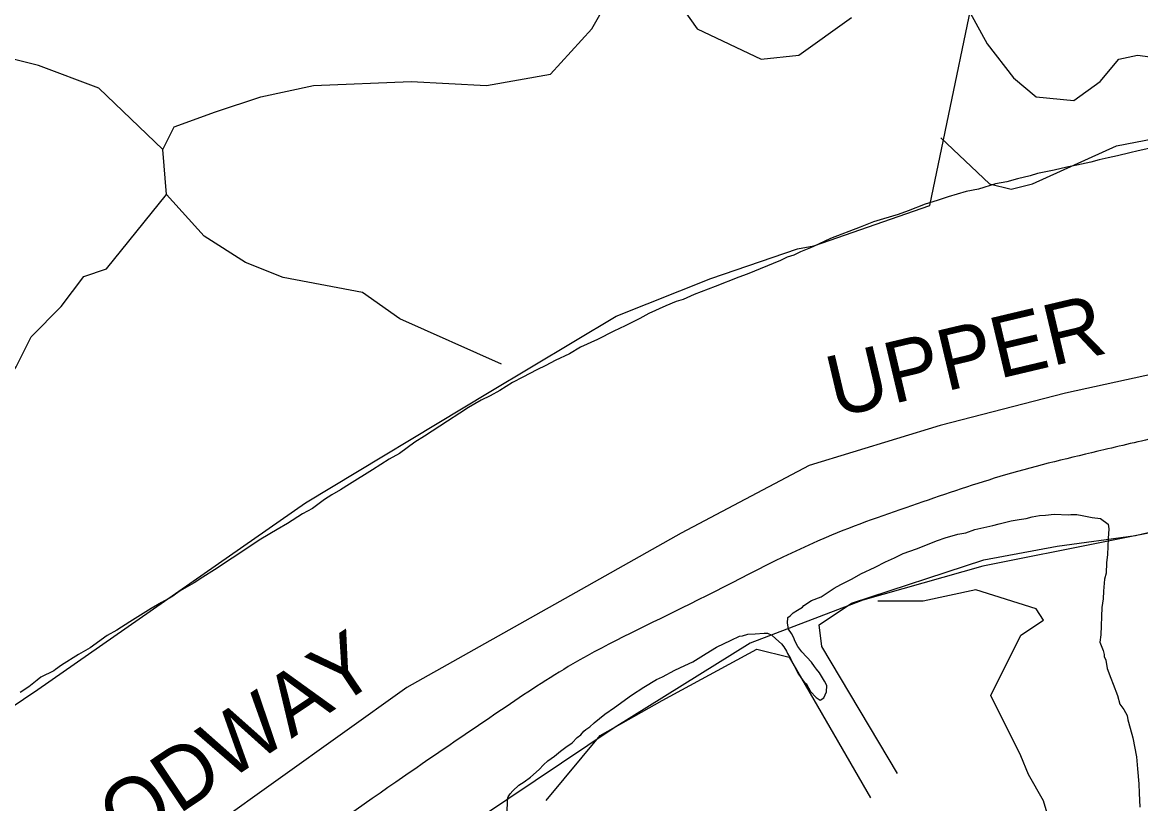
# Model space of a CAD drawing. Extents: x 3161514 to 3199414, y 831166 to 856601.
# Drawn here: x 3178562 to 3180393, y 837968 to 839247 of the extents above; entities that cross this region are included whole.
import ezdxf

# ---------------------------------------------------------------- set-up
doc = ezdxf.new("R2010")
doc.units = 0
for name, color, linetype in [('V-LEVE-IDEN', 7, 'Continuous'), ('V-LEVE-TOET', 7, 'Continuous'), ('V-ROAD-CNTR', 7, 'Continuous'), ('V-SITE-VEGE', 7, 'Continuous'), ('V-TOPO-SHOR', 7, 'Continuous')]:
    doc.layers.add(name, color=color, linetype=linetype)

msp = doc.modelspace()

# ---------------------------------------------------------------- linework, layer by layer
at = {"layer": 'V-LEVE-TOET'}
for points in [[(3182134.4, 838632), (3181835.3, 838669.5), (3181620, 838702.2), (3181419, 838738.9), (3181215.2, 838746.4), (3181018.9, 838763), (3180852.1, 838746.4), (3180663.8, 838718.4), (3180482, 838686.2), (3180269.4, 838640), (3180064.4, 838587.3), (3179849.8, 838521.6), (3179640.2, 838410.8), (3179467.7, 838313.8), (3179190.9, 838158.2), (3178769.9, 837857.1), (3178281.9, 837512.4), (3177987.2, 837338), (3177625.9, 837102.4), (3177272.4, 836861), (3176982.8, 836651), (3176907.6, 836601.9)], [(3180760.8, 838480.3), (3180711.4, 838475.9), (3180547.6, 838439), (3180336.5, 838397), (3180134.1, 838356.8), (3179937.9, 838301.5), (3179753, 838230.7), (3179530.3, 838092.6), (3179228.7, 837890), (3178834.5, 837622), (3178357.2, 837294.9), (3177857, 836952.5), (3177339.2, 836600.7)]]:
    msp.add_lwpolyline(points, dxfattribs=at)
at = {"layer": 'V-ROAD-CNTR'}
msp.add_spline([(3185247.7, 837950), (3185220.1, 837952.3), (3184919.5, 838004.8), (3184339.6, 838108.5), (3183779, 838207.2), (3183367, 838284.1), (3182794.1, 838383.3), (3182428.7, 838447.8), (3182275.5, 838472.5), (3181998.8, 838523), (3181803.1, 838555.1), (3181641.5, 838586.6), (3181550.7, 838598.2), (3181445.6, 838611.4), (3181325.6, 838620), (3181174.8, 838631.9), (3181016.7, 838639.1), (3180880.4, 838632.5), (3180707.8, 838613), (3180579.6, 838596.6), (3180431.4, 838569.9), (3180332.4, 838547.3), (3180171.1, 838506.1), (3180026.7, 838458.9), (3179877.5, 838403.8), (3179654.2, 838294.6), (3179462.8, 838196.9), (3179346.3, 838121.9), (3179173.3, 838003.7), (3178965.2, 837857.6), (3178757.9, 837712.7), (3178391.8, 837460.5), (3178085.3, 837254.5), (3177675.2, 836977.6), (3177220.5, 836675.6), (3177123, 836609.3)], degree=3, dxfattribs=at)
at = {"layer": 'V-SITE-VEGE'}
for p, q in [((3180236.6, 838440.4), (3180251.2, 838441.8)), ((3180251.2, 838441.8), (3180274.5, 838440.9)), ((3180274.5, 838440.9), (3180278.4, 838441.7)), ((3180278.4, 838441.7), (3180288.1, 838441.3)), ((3180130.7, 838419.3), (3180150.3, 838423.4)), ((3180150.3, 838423.4), (3180161.1, 838425.9)), ((3180161.1, 838425.9), (3180180.8, 838430.9)), ((3180180.8, 838430.9), (3180193.5, 838433.3)), ((3180193.5, 838433.3), (3180205.2, 838434.8)), ((3180205.2, 838434.8), (3180215.1, 838437.4)), ((3180215.1, 838437.4), (3180226.8, 838439.8)), ((3180226.8, 838439.8), (3180236.6, 838440.4)), ((3180288.1, 838441.3), (3180296.8, 838440)), ((3180296.8, 838440), (3180313.2, 838436.5)), ((3180313.2, 838436.5), (3180326.8, 838435)), ((3180326.8, 838435), (3180339.1, 838425.7)), ((3180339.1, 838425.7), (3180340.7, 838417.9)), ((3180072.7, 838403), (3180093.4, 838409)), ((3180093.4, 838409), (3180106.1, 838411.5)), ((3180106.1, 838411.5), (3180120.9, 838416.7)), ((3180120.9, 838416.7), (3180130.7, 838419.3)), ((3180340.7, 838417.9), (3180339.1, 838402.4)), ((3180025.4, 838385.4), (3180059.9, 838398.7)), ((3180059.9, 838398.7), (3180072.7, 838403)), ((3180339.1, 838402.4), (3180338.1, 838376.2)), ((3179975, 838364.1), (3179989.8, 838370.3)), ((3179989.8, 838370.3), (3180003.7, 838377.5)), ((3180003.7, 838377.5), (3180025.4, 838385.4)), ((3180338.1, 838376.2), (3180336.6, 838362.6)), ((3179934.3, 838344.3), (3179958.1, 838355)), ((3179958.1, 838355), (3179975, 838364.1)), ((3180336.6, 838362.6), (3180335.9, 838345.2)), ((3179901.6, 838327.1), (3179920.4, 838336.1)), ((3179920.4, 838336.1), (3179934.3, 838344.3)), ((3180333.6, 838335.5), (3180331.9, 838316.2)), ((3180335.9, 838345.2), (3180333.6, 838335.5)), ((3179869.7, 838306.9), (3179890.6, 838320.7)), ((3179890.6, 838320.7), (3179901.6, 838327.1)), ((3180331.9, 838316.2), (3180331.4, 838303.5)), ((3179840.9, 838292.5), (3179853.9, 838300.7)), ((3179853.9, 838300.7), (3179869.7, 838306.9)), ((3180331.4, 838303.5), (3180328.9, 838289)), ((3179818.9, 838275.8), (3179823.9, 838280.5)), ((3179823.9, 838280.5), (3179830.9, 838285.1)), ((3179830.9, 838285.1), (3179838.9, 838289.6)), ((3179838.9, 838289.6), (3179840.9, 838292.5)), ((3180328.9, 838289), (3180327.1, 838244.4)), ((3179814.5, 838263.4), (3179814.9, 838273.1)), ((3179815.2, 838257.5), (3179814.5, 838263.4)), ((3179814.9, 838273.1), (3179818.9, 838275.8)), ((3179722, 838235.8), (3179735.9, 838242.1)), ((3179735.9, 838242.1), (3179740.8, 838242.9)), ((3179740.8, 838242.9), (3179749.6, 838245.5)), ((3179749.6, 838245.5), (3179761.3, 838246)), ((3179761.3, 838246), (3179776, 838247.4)), ((3179776, 838247.4), (3179781.8, 838247.1)), ((3179781.8, 838247.1), (3179788.5, 838244)), ((3179788.5, 838244), (3179795, 838237.9)), ((3179816.1, 838253.6), (3179815.2, 838257.5)), ((3179820.7, 838246.6), (3179816.1, 838253.6)), ((3179824.3, 838240.6), (3179820.7, 838246.6)), ((3179827, 838233.7), (3179824.3, 838240.6)), ((3180327.1, 838244.4), (3180325.7, 838232.8)), ((3179681.3, 838214.1), (3179698.2, 838224.1)), ((3179698.2, 838224.1), (3179722, 838235.8)), ((3179795, 838237.9), (3179804.4, 838229.7)), ((3179804.4, 838229.7), (3179808.1, 838224.7)), ((3179808.1, 838224.7), (3179812.7, 838217.7)), ((3179831.5, 838225.7), (3179827, 838233.7)), ((3179838, 838216.7), (3179831.5, 838225.7)), ((3180325.7, 838232.8), (3180331, 838219)), ((3179659.4, 838200.4), (3179681.3, 838214.1)), ((3179812.7, 838217.7), (3179814.5, 838213.8)), ((3179814.5, 838213.8), (3179819.1, 838205.8)), ((3179819.1, 838205.8), (3179826.3, 838191.9)), ((3179853.8, 838199.6), (3179838, 838216.7)), ((3180331, 838219), (3180332.7, 838212.1)), ((3180332.7, 838212.1), (3180332.6, 838209.2)), ((3180332.6, 838209.2), (3180335.3, 838203.2)), ((3179609.8, 838176), (3179629.7, 838186.9)), ((3179629.7, 838186.9), (3179646.5, 838194.1)), ((3179646.5, 838194.1), (3179659.4, 838200.4)), ((3179826.3, 838191.9), (3179832.6, 838180)), ((3179858.4, 838192.6), (3179853.8, 838199.6)), ((3179862.1, 838188.6), (3179858.4, 838192.6)), ((3179866.8, 838182.6), (3179862.1, 838188.6)), ((3180335.3, 838203.2), (3180337.6, 838189.5)), ((3180337.6, 838189.5), (3180343.8, 838173.7)), ((3179579, 838158.8), (3179599.9, 838171.6)), ((3179599.9, 838171.6), (3179609.8, 838176)), ((3179832.6, 838180), (3179841.9, 838167)), ((3179841.9, 838167), (3179844.7, 838165)), ((3179875, 838168.6), (3179866.8, 838182.6)), ((3179878.6, 838161.7), (3179875, 838168.6)), ((3180343.8, 838173.7), (3180347.3, 838163.9)), ((3179559.1, 838145.9), (3179579, 838158.8)), ((3179844.7, 838165), (3179852, 838152)), ((3179852, 838152), (3179861.3, 838141.9)), ((3179873.9, 838141.5), (3179878.2, 838151)), ((3179878.2, 838151), (3179878.6, 838161.7)), ((3180347.3, 838163.9), (3180354.4, 838145.1)), ((3179531.1, 838125.6), (3179559.1, 838145.9)), ((3179861.3, 838141.9), (3179868, 838137.8)), ((3179868, 838137.8), (3179873.9, 838141.5)), ((3180354.4, 838145.1), (3180358.7, 838131.3)), ((3180358.7, 838131.3), (3180365.2, 838122.3)), ((3179498, 838100.7), (3179515.1, 838114.6)), ((3179515.1, 838114.6), (3179531.1, 838125.6)), ((3180365.2, 838122.3), (3180370.6, 838112.4)), ((3180370.6, 838112.4), (3180371.3, 838105.6)), ((3179484, 838089.5), (3179490.9, 838094.1)), ((3179490.9, 838094.1), (3179498, 838100.7)), ((3180371.3, 838105.6), (3180375.6, 838091.8)), ((3179461.7, 838068), (3179469.8, 838076.5)), ((3179469.8, 838076.5), (3179475.9, 838081.1)), ((3179475.9, 838081.1), (3179480.9, 838086.7)), ((3179480.9, 838086.7), (3179484, 838089.5)), ((3180375.6, 838091.8), (3180379.9, 838076.1)), ((3180379.9, 838076.1), (3180385.5, 838044.7)), ((3179442.7, 838054.2), (3179451.7, 838060.7)), ((3179451.7, 838060.7), (3179461.7, 838068)), ((3179421.7, 838038.5), (3179432.7, 838045.8)), ((3179432.7, 838045.8), (3179442.7, 838054.2)), ((3180385.5, 838044.7), (3180387.6, 838025.2)), ((3179393.4, 838011.4), (3179407.5, 838024.4)), ((3179407.5, 838024.4), (3179414.6, 838032)), ((3179414.6, 838032), (3179421.7, 838038.5)), ((3180387.6, 838025.2), (3180389.6, 838000.8)), ((3179374.4, 837998.5), (3179383.4, 838004)), ((3179383.4, 838004), (3179393.4, 838011.4)), ((3179357.2, 837979.7), (3179360.3, 837984.5)), ((3179360.3, 837984.5), (3179364.4, 837989.2)), ((3179364.4, 837989.2), (3179374.4, 837998.5)), ((3180389.6, 838000.8), (3180390, 837985.3)), ((3180390, 837985.3), (3180391.1, 837962.8)), ((3179355.3, 837956.5), (3179355.8, 837970.1)), ((3179355.8, 837970.1), (3179356.1, 837975.9)), ((3179356.1, 837975.9), (3179357.2, 837979.7))]:
    msp.add_line(p, q, dxfattribs=at)
for points in [[(3180410.9, 839041.6), (3180388.3, 839036.6), (3180374.6, 839033.2), (3180354.9, 839028.2), (3180339.3, 839024.9), (3180324.5, 839021.6), (3180310.8, 839018.2), (3180288.2, 839013.3), (3180271.6, 839010), (3180251, 839005), (3180240.2, 839002.5), (3180223.5, 838999.3), (3180211.7, 838995.8), (3180191.1, 838990.8), (3180173.4, 838985.6), (3180154.8, 838982.5), (3180127.3, 838973.8), (3180106.7, 838969.8), (3180077.2, 838961.2), (3180059.4, 838955.1), (3180039.8, 838949), (3180012.1, 838938.4), (3179995.3, 838932.3), (3179971.7, 838925.4), (3179955, 838920.3), (3179933.3, 838911.4), (3179884.9, 838892.8), (3179865.1, 838883.9), (3179852.2, 838877.6), (3179835.5, 838871.4), (3179824.6, 838866), (3179813.7, 838862.5), (3179802.8, 838857.1), (3179748.5, 838834.9), (3179734.7, 838829.6), (3179696.2, 838814.6), (3179661.6, 838801.4), (3179643.8, 838793.3), (3179632, 838789.9), (3179615.2, 838782.8), (3179587.5, 838770.2), (3179572.6, 838762.1), (3179548.8, 838750.3), (3179530, 838741.4), (3179503.2, 838727.8), (3179475.5, 838715.3), (3179457.5, 838704.3), (3179433.8, 838693.6), (3179418.9, 838685.4), (3179404, 838678.2), (3179381.2, 838666.4), (3179364.3, 838657.4), (3179343.4, 838644.6), (3179327.5, 838635.5), (3179312.6, 838628.3), (3179291.8, 838616.4), (3179277.8, 838607.3), (3179257.8, 838594.4), (3179219.9, 838569.7), (3179204, 838559.6), (3179179, 838541.1), (3179162.1, 838532), (3179135.1, 838514.6), (3179097.3, 838490.8), (3179082.3, 838481.7), (3179068.4, 838473.5), (3179056.4, 838466.1), (3179036.4, 838451.4), (3179020.5, 838442.3), (3178995.6, 838426.7), (3178978.7, 838416.7), (3178951.8, 838401.2)], [(3178951.8, 838401.2), (3178937.9, 838392), (3178917.9, 838378.2), (3178904.9, 838370), (3178876, 838350.7), (3178857, 838338.8), (3178843.1, 838329.6), (3178820.2, 838316.8), (3178806.2, 838306.7), (3178789.3, 838297.6), (3178772.4, 838287.6), (3178750.5, 838273.9), (3178737.5, 838265.6), (3178716.5, 838251.9), (3178700.7, 838243.7), (3178672.7, 838223.4), (3178653.8, 838212.5), (3178625.9, 838195.1), (3178615.8, 838187.7), (3178612.9, 838185.9), (3178592, 838175), (3178586, 838170.4), (3178572, 838159.3), (3178558, 838150.1)]]:
    msp.add_lwpolyline(points, dxfattribs=at)
at = {"layer": 'V-TOPO-SHOR'}
for points in [[(3176825.1, 836964.2), (3176829.5, 836990.8), (3176869.4, 837026.2), (3177037.6, 837128), (3177165.9, 837216.5), (3178356.6, 838000), (3178586.8, 838154.9), (3179025, 838460.3), (3179326, 838641.8), (3179534.1, 838765.7), (3179689, 838827.7), (3179830.6, 838876.4), (3179857.2, 838880.8), (3180047.5, 838947.2), (3180144.9, 839416.4)], [(3180104.2, 839279.2), (3180141.1, 839211.4), (3180184.3, 839155.9), (3180221.3, 839125.1), (3180282.9, 839118.9), (3180326, 839149.8), (3180356.8, 839186.7), (3180387.6, 839192.9), (3180436.9, 839186.7), (3180504.7, 839168.2), (3180535.5, 839186.7), (3180560.2, 839236), (3180584.8, 839303.8)], [(3179346.3, 838687.6), (3179179.9, 838761.6), (3179118.3, 838804.7), (3178988.9, 838829.3), (3178927.2, 838854), (3178859.5, 838897.1), (3178797.8, 838964.9), (3178791.7, 839038.8), (3178810.2, 839075.8), (3178878, 839100.5), (3178951.9, 839125.1), (3179038.2, 839143.6), (3179198.4, 839149.8), (3179321.6, 839143.6), (3179426.4, 839162.1), (3179494.1, 839236), (3179518.8, 839279.2)], [(3179635.9, 839279.2), (3179666.7, 839236), (3179771.4, 839186.7), (3179833, 839192.9), (3179919.3, 839254.5)], [(3178791.7, 839038.8), (3178686.9, 839139), (3178588.3, 839175.9), (3178489.8, 839200.6), (3178317.2, 839188.3), (3178218.6, 839188.3), (3178095.4, 839188.3), (3177984.5, 839188.3), (3177935.2, 839188.3), (3177885.9, 839225.2), (3177787.3, 839225.2), (3177713.3, 839200.6), (3177676.4, 839139), (3177664.1, 839065), (3177639.4, 839040.4), (3177627.1, 839015.7), (3177627.1, 838880.2), (3177614.8, 838769.3), (3177590.1, 838683), (3177503.8, 838596.7), (3177503.8, 838584.4), (3177479.2, 838510.5), (3177454.5, 838448.8), (3177405.3, 838399.5)], [(3180065.2, 839057.9), (3180144.9, 838982.6), (3180180.3, 838973.8), (3180215.7, 838982.6), (3180352.9, 839044.6), (3180698.2, 839111), (3180901.8, 839124.3), (3181114.3, 839142), (3181242.6, 839137.6), (3181410.8, 839126.5)], [(3177725.7, 837783.4), (3177885.9, 837881.9), (3177972.2, 838005.2), (3177984.5, 838066.8), (3178083.1, 838091.4), (3178157, 838091.4), (3178255.6, 838153.1), (3178366.5, 838251.7), (3178428.1, 838325.6), (3178514.4, 838411.9), (3178526.7, 838510.5), (3178514.4, 838572.1), (3178526.7, 838646), (3178551.4, 838683), (3178576, 838732.3), (3178625.3, 838781.6), (3178662.3, 838830.9), (3178699.3, 838843.2), (3178797.8, 838964.9)], [(3179994.4, 838017.7), (3179870.5, 838225.7), (3179866, 838261.1), (3179919.2, 838296.5), (3180136, 838367.4), (3180255.6, 838389.5), (3180383.9, 838407.2), (3180534.4, 838442.6), (3180715.9, 838469.2)], [(3180412.3, 837295), (3180369.1, 837436.7), (3180338.3, 837510.7), (3180301.4, 837566.1), (3180270.5, 837633.9), (3180264.4, 837714), (3180264.4, 837794.1), (3180264.4, 837868.1), (3180233.6, 837972.8), (3180208.9, 838016), (3180196.6, 838046.8), (3180147.3, 838145.4), (3180196.6, 838244), (3180233.6, 838268.6), (3180221.3, 838287.1), (3180122.7, 838317.9), (3180036.4, 838299.4), (3179962.4, 838299.4)], [(3179419, 837973.4), (3179507.5, 838079.7), (3179609.3, 838137.2), (3179764.2, 838221.3), (3179817.3, 838208), (3179950.1, 837977.8)]]:
    msp.add_lwpolyline(points, dxfattribs=at)

# ---------------------------------------------------------------- texts
at = {"layer": 'V-LEVE-IDEN'}
for s, rotation, p in [('UPPER', 13.3245, (3179892.8, 838599.9)), ('MORGANZA   FLOODWAY', 33.9629, (3177782, 837252.4))]:
    msp.add_text(s, height=100, rotation=rotation, dxfattribs=at).set_placement(p)

doc.saveas('drawing.dxf')
